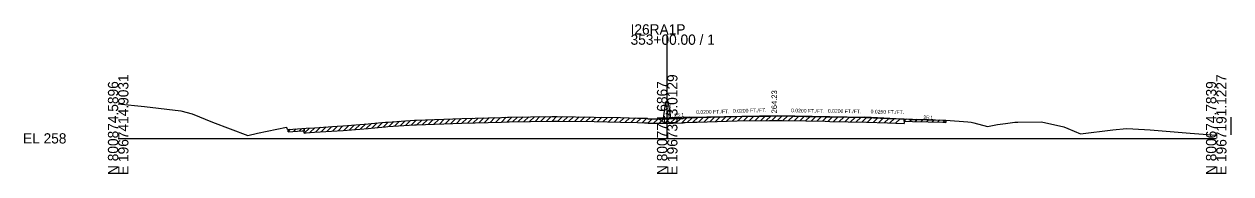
# Model space of a CAD drawing. Extents: x -26 to 304, y -10 to 7527.
# Drawn here: x -25.7 to 304, y 1490.3 to 1531.2 of the extents above; entities that cross this region are included whole.
import ezdxf

# ---------------------------------------------------------------- set-up
doc = ezdxf.new("R2010")
doc.units = 0
for name, color, linetype in [('RD_GPK_XS_Cell', 7, 'Continuous'), ('RD_XS_Base', 7, 'Continuous'), ('RD_XS_EarthShd', 7, 'Continuous'), ('RD_XS_ExGround', 7, 'Continuous'), ('RD_XS_ExPaveRet', 7, 'Continuous'), ('RD_XS_Misc_Line', 7, 'Continuous'), ('RD_XS_Pave', 7, 'Continuous'), ('RD_XS_PaveShd', 7, 'Continuous'), ('RD_XS_TX_Elev_EX', 7, 'Continuous'), ('RD_XS_TX_Elev_PR', 7, 'Continuous'), ('RD_XS_TX_MkPT', 7, 'Continuous'), ('RD_XS_TX_Profile', 7, 'Continuous'), ('RD_XS_TX_Station', 7, 'Continuous')]:
    doc.layers.add(name, color=color, linetype=linetype)

msp = doc.modelspace()

# ---------------------------------------------------------------- linework, layer by layer
at = {"layer": 'RD_GPK_XS_Cell'}
for p, q in [((150, 1500), (150, 1528.36)), ((0, 1500), (150, 1500)), ((150, 1500), (300, 1500))]:
    msp.add_line(p, q, dxfattribs=at)
at = {"layer": 'RD_XS_Base'}
msp.add_line((150, 1505.38), (150, 1505.51), dxfattribs=at)
at = {"layer": 'RD_XS_EarthShd'}
for p, q in [((149, 1505.53), (149.67, 1510.01)), ((150, 1510.01), (149.67, 1510.01)), ((150, 1510.01), (150.33, 1510.01)), ((151, 1505.53), (150.33, 1510.01))]:
    msp.add_line(p, q, dxfattribs=at)
at = {"layer": 'RD_XS_ExGround'}
msp.add_lwpolyline([(0, 1509.45), (7.22, 1508.68), (17.14, 1507.55), (20.26, 1506.67), (25.76, 1504.4), (35.44, 1500.79), (38.03, 1501.39), (46.02, 1503.04), (46.12, 1502.59), (46.44, 1502.45), (50.29, 1502.65), (51.38, 1502.76), (53.68, 1502.91), (59.81, 1503.34), (61.46, 1503.4), (68.3, 1503.99), (69.16, 1504.06), (73.08, 1504.4), (73.66, 1504.46), (80.92, 1504.93), (81.5, 1504.95), (93.87, 1505.39), (104.74, 1505.71), (106.37, 1505.77), (106.85, 1505.78), (118.51, 1505.99), (119.97, 1505.96), (130.09, 1505.82), (137.25, 1505.66), (141.88, 1505.56), (143.82, 1505.5), (144.5, 1505.48), (144.82, 1505.37), (145.25, 1505.36), (148.39, 1505.36), (150, 1505.38), (151.09, 1505.4), (151.59, 1505.41), (154.34, 1505.45), (154.55, 1505.57), (154.93, 1505.58), (157.3, 1505.67), (158.21, 1505.7), (169.08, 1506.01), (177.94, 1506.1), (181.29, 1506.13), (187.84, 1506.01), (193.12, 1505.92), (194.46, 1505.89), (204.49, 1505.67), (210.21, 1505.47), (217.02, 1505.24), (221.32, 1505.13), (225.33, 1505.01), (226.17, 1504.98), (232.13, 1504.48), (233.06, 1504.4), (233.8, 1504.22), (237.48, 1503.27), (240.28, 1503.75), (242.39, 1504.07), (244.94, 1504.45), (245.79, 1504.38), (252.3, 1504.48), (258.38, 1503.19), (259.46, 1502.71), (262.93, 1501.22), (271.75, 1502.35), (275.46, 1502.72), (277.21, 1502.62), (281.98, 1502.37), (292.92, 1501.4), (299.95, 1500.84), (300, 1500.83)], dxfattribs=at)
at = {"layer": 'RD_XS_ExPaveRet'}
for p, q in [((73.66, 1503.21), (80.92, 1503.68)), ((80.92, 1503.68), (81.5, 1503.7)), ((81.5, 1503.7), (93.87, 1504.14)), ((93.87, 1504.14), (104.74, 1504.46)), ((104.74, 1504.46), (106.37, 1504.52)), ((106.37, 1504.52), (106.85, 1504.53)), ((106.85, 1504.53), (118.51, 1504.74)), ((118.51, 1504.74), (119.97, 1504.71)), ((119.97, 1504.71), (130.09, 1504.57)), ((130.09, 1504.57), (137.25, 1504.41)), ((137.25, 1504.41), (141.88, 1504.31)), ((141.88, 1504.31), (143.82, 1504.25)), ((143.82, 1504.25), (144.5, 1504.23)), ((144.5, 1504.23), (144.82, 1504.12)), ((144.82, 1504.12), (145.25, 1504.11)), ((145.25, 1504.11), (148.39, 1504.11)), ((148.39, 1504.11), (150, 1504.13)), ((150, 1504.13), (151.09, 1504.15)), ((151.09, 1504.15), (151.59, 1504.16)), ((151.59, 1504.16), (154.34, 1504.2)), ((154.34, 1504.2), (154.55, 1504.32)), ((154.55, 1504.32), (154.93, 1504.33)), ((154.93, 1504.33), (157.3, 1504.42)), ((157.3, 1504.42), (158.21, 1504.45)), ((158.21, 1504.45), (169.08, 1504.76)), ((169.08, 1504.76), (177.94, 1504.85)), ((177.94, 1504.85), (181.29, 1504.88)), ((181.29, 1504.88), (187.84, 1504.76)), ((187.84, 1504.76), (193.12, 1504.67)), ((193.12, 1504.67), (194.46, 1504.64)), ((194.46, 1504.64), (204.49, 1504.42)), ((204.49, 1504.42), (210.21, 1504.22)), ((210.21, 1504.22), (214.76, 1504.06)), ((214.76, 1505.31), (214.76, 1504.06)), ((214.76, 1504.69), (214.76, 1505.31)), ((214.76, 1504.69), (217.02, 1504.61)), ((217.02, 1504.61), (221.32, 1504.5)), ((221.32, 1504.5), (225.33, 1504.38)), ((225.33, 1504.38), (226.17, 1504.35)), ((226.17, 1504.98), (226.17, 1504.35)), ((46.44, 1501.83), (46.44, 1502.45)), ((46.44, 1501.83), (50.29, 1502.03)), ((50.29, 1502.03), (50.85, 1502.08)), ((50.85, 1501.46), (50.85, 1502.71)), ((50.85, 1502.71), (50.85, 1502.08)), ((50.85, 1501.46), (51.38, 1501.51)), ((51.38, 1501.51), (53.68, 1501.66)), ((53.68, 1501.66), (59.81, 1502.09)), ((59.81, 1502.09), (61.46, 1502.15)), ((61.46, 1502.15), (68.3, 1502.74)), ((68.3, 1502.74), (69.16, 1502.81)), ((69.16, 1502.81), (73.08, 1503.15)), ((73.08, 1503.15), (73.66, 1503.21))]:
    msp.add_line(p, q, dxfattribs=at)
at = {"layer": 'RD_XS_Misc_Line'}
for p, q in [((60.08, 1502.1), (61.42, 1503.4)), ((61.62, 1502.17), (63.02, 1503.54)), ((63.16, 1502.3), (64.56, 1503.67)), ((64.69, 1502.43), (66.1, 1503.8)), ((66.23, 1502.57), (67.64, 1503.94)), ((67.77, 1502.7), (69.17, 1504.06)), ((69.31, 1502.82), (70.72, 1504.2)), ((70.85, 1502.96), (72.26, 1504.33)), ((72.39, 1503.09), (73.8, 1504.47)), ((73.93, 1503.23), (75.3, 1504.57)), ((75.46, 1503.33), (76.84, 1504.67)), ((77, 1503.43), (78.37, 1504.76)), ((78.54, 1503.52), (79.91, 1504.86)), ((80.08, 1503.62), (81.44, 1504.94)), ((81.62, 1503.7), (82.95, 1505)), ((83.16, 1503.76), (84.49, 1505.05)), ((84.7, 1503.81), (86.03, 1505.11)), ((86.23, 1503.87), (87.57, 1505.17)), ((87.77, 1503.92), (89.1, 1505.22)), ((89.31, 1503.98), (90.64, 1505.28)), ((90.85, 1504.03), (92.18, 1505.33)), ((92.39, 1504.09), (93.72, 1505.39)), ((93.93, 1504.15), (95.25, 1505.43)), ((95.47, 1504.19), (96.79, 1505.48)), ((97, 1504.24), (98.33, 1505.53)), ((98.54, 1504.28), (99.86, 1505.57)), ((100.08, 1504.33), (101.4, 1505.62)), ((101.62, 1504.37), (102.94, 1505.66)), ((103.16, 1504.42), (104.48, 1505.71)), ((104.7, 1504.46), (106.02, 1505.75)), ((106.24, 1504.51), (107.55, 1505.79)), ((107.77, 1504.54), (109.08, 1505.82)), ((109.31, 1504.57), (110.62, 1505.84)), ((110.85, 1504.6), (112.16, 1505.87)), ((112.39, 1504.63), (113.7, 1505.9)), ((113.93, 1504.65), (115.23, 1505.93)), ((115.47, 1504.68), (116.77, 1505.95)), ((117.01, 1504.71), (118.31, 1505.98)), ((118.54, 1504.74), (119.8, 1505.96)), ((120.08, 1504.71), (121.35, 1505.94)), ((121.62, 1504.69), (122.88, 1505.92)), ((123.16, 1504.67), (124.42, 1505.9)), ((124.7, 1504.64), (125.96, 1505.88)), ((126.24, 1504.62), (127.5, 1505.85)), ((127.78, 1504.6), (129.04, 1505.83)), ((129.31, 1504.58), (130.57, 1505.81)), ((130.85, 1504.55), (132.11, 1505.77)), ((132.39, 1504.52), (133.65, 1505.74)), ((133.93, 1504.48), (135.18, 1505.7)), ((135.47, 1504.45), (136.72, 1505.67)), ((137.01, 1504.42), (138.26, 1505.64)), ((138.55, 1504.38), (139.8, 1505.6)), ((140.08, 1504.35), (141.34, 1505.57)), ((141.62, 1504.31), (142.87, 1505.53)), ((143.16, 1504.27), (144.4, 1505.48)), ((144.7, 1504.16), (145.93, 1505.36)), ((146.24, 1504.11), (147.52, 1505.36)), ((147.78, 1504.11), (149.07, 1505.37)), ((149.32, 1504.12), (150.62, 1505.39)), ((150.85, 1504.15), (152.15, 1505.41)), ((152.39, 1504.17), (153.69, 1505.44)), ((153.93, 1504.19), (155.38, 1505.6)), ((155.47, 1504.35), (156.8, 1505.65)), ((157.01, 1504.41), (158.33, 1505.7)), ((158.55, 1504.46), (159.87, 1505.74)), ((160.09, 1504.5), (161.41, 1505.79)), ((161.62, 1504.54), (162.94, 1505.83)), ((163.16, 1504.59), (164.48, 1505.88)), ((164.7, 1504.63), (166.02, 1505.92)), ((166.24, 1504.68), (167.56, 1505.96)), ((167.78, 1504.72), (169.1, 1506.01)), ((169.32, 1504.76), (170.61, 1506.02)), ((170.86, 1504.78), (172.15, 1506.04)), ((172.39, 1504.79), (173.69, 1506.05)), ((173.93, 1504.81), (175.23, 1506.07)), ((175.47, 1504.82), (176.77, 1506.08)), ((177.01, 1504.84), (178.3, 1506.1)), ((178.55, 1504.85), (179.84, 1506.11)), ((180.09, 1504.87), (181.38, 1506.12)), ((181.63, 1504.87), (182.89, 1506.1)), ((183.16, 1504.84), (184.42, 1506.07)), ((184.7, 1504.82), (185.96, 1506.05)), ((186.24, 1504.79), (187.5, 1506.02)), ((187.78, 1504.76), (189.04, 1505.99)), ((189.32, 1504.74), (190.58, 1505.96)), ((190.86, 1504.71), (192.12, 1505.94)), ((192.4, 1504.68), (193.65, 1505.91)), ((193.93, 1504.65), (195.19, 1505.87)), ((195.47, 1504.61), (196.73, 1505.84)), ((197.01, 1504.58), (198.27, 1505.8)), ((198.55, 1504.55), (199.8, 1505.77)), ((200.09, 1504.51), (201.34, 1505.73)), ((201.63, 1504.48), (202.88, 1505.7)), ((203.17, 1504.44), (204.42, 1505.67)), ((204.7, 1504.41), (205.94, 1505.62)), ((206.24, 1504.35), (207.48, 1505.56)), ((207.78, 1504.3), (209.02, 1505.51)), ((209.32, 1504.25), (210.56, 1505.46)), ((210.86, 1504.2), (212.1, 1505.4)), ((212.4, 1504.14), (213.64, 1505.35)), ((214.76, 1504.69), (215.38, 1505.29)), ((216.28, 1504.64), (216.9, 1505.24)), ((217.8, 1504.59), (218.42, 1505.2)), ((219.33, 1504.55), (219.94, 1505.16)), ((220.85, 1504.52), (221.46, 1505.12)), ((222.37, 1504.47), (222.98, 1505.08)), ((223.89, 1504.42), (224.5, 1505.03)), ((225.41, 1504.38), (226.02, 1504.98)), ((46.44, 1501.83), (47.11, 1502.49)), ((47.96, 1501.91), (48.63, 1502.57)), ((49.48, 1501.99), (50.15, 1502.65)), ((50.85, 1501.46), (52.24, 1502.81)), ((52.39, 1501.57), (53.76, 1502.91)), ((53.92, 1501.67), (55.31, 1503.02)), ((55.46, 1501.78), (56.84, 1503.13)), ((57, 1501.89), (58.38, 1503.24)), ((58.54, 1502), (59.92, 1503.34))]:
    msp.add_line(p, q, dxfattribs=at)
at = {"layer": 'RD_XS_Pave'}
for p, q in [((156, 1505.75), (180, 1506.23)), ((180, 1506.23), (204, 1505.75)), ((216, 1505.17), (204, 1505.75)), ((304, 1505.75), (304, 1500.96))]:
    msp.add_line(p, q, dxfattribs=at)
at = {"layer": 'RD_XS_PaveShd'}
for p, q in [((156, 1505.75), (150, 1505.51)), ((216, 1505.17), (226, 1504.98))]:
    msp.add_line(p, q, dxfattribs=at)
at = {"layer": 'RD_XS_TX_Elev_PR'}
for p, q in [((150, 1505.38), (151.09, 1505.4)), ((151.09, 1505.4), (151.59, 1505.41)), ((151.59, 1505.41), (154.34, 1505.45)), ((154.34, 1505.45), (154.55, 1505.57)), ((154.55, 1505.57), (154.93, 1505.58)), ((154.93, 1505.58), (157.3, 1505.67)), ((157.3, 1505.67), (158.21, 1505.7)), ((158.21, 1505.7), (169.08, 1506.01)), ((169.08, 1506.01), (177.94, 1506.1)), ((177.94, 1506.1), (181.29, 1506.13)), ((181.29, 1506.13), (187.84, 1506.01)), ((187.84, 1506.01), (193.12, 1505.92)), ((193.12, 1505.92), (194.46, 1505.89)), ((194.46, 1505.89), (204.49, 1505.67)), ((204.49, 1505.67), (210.21, 1505.47)), ((210.21, 1505.47), (214.76, 1505.31)), ((214.76, 1505.31), (217.02, 1505.24)), ((217.02, 1505.24), (219.17, 1505.18)), ((219.17, 1505.18), (221.32, 1505.13)), ((221.32, 1505.13), (223.32, 1505.07)), ((223.32, 1505.07), (225.33, 1505.01)), ((225.33, 1505.01), (226, 1504.98))]:
    msp.add_line(p, q, dxfattribs=at)

# ---------------------------------------------------------------- texts
at = {"layer": 'RD_GPK_XS_Cell'}
for s, p in [('I26RA1P', (140, 1528.36)), ('353+00.00 / 1', (140, 1525.56)), ('EL 258', (-26, 1498.6))]:
    msp.add_text(s, height=2.8, dxfattribs=at).set_placement(p)
for s, p in [('E 1967414.9031', (2.8, 1490)), ('E 1967303.0129', (152.8, 1490)), ('E 1967191.1227', (302.8, 1490)), ('N 800874.5896', (0, 1490)), ('N 800774.6867', (150, 1490)), ('N 800674.7839', (300, 1490))]:
    msp.add_text(s, height=2.8, rotation=90, dxfattribs=at).set_placement(p)
at = {"layer": 'RD_XS_TX_Elev_EX'}
msp.add_text('263.38', height=1, rotation=90, dxfattribs=at).set_placement((151, 1505.38))
at = {"layer": 'RD_XS_TX_MkPT'}
for rotation, p in [(2.2906, (151.94, 1505.83)), (357.7094, (219.96, 1505.26))]:
    msp.add_text('25:1', height=1, rotation=rotation, dxfattribs=at).set_placement(p)
at = {"layer": 'RD_XS_TX_Profile'}
for s, rotation, p in [('0.0200 FT./FT.', 1.1458, (157.92, 1506.67)), ('0.0200 FT./FT.', 1.1458, (167.98, 1506.99)), ('0.0200 FT./FT.', 358.5679, (183.83, 1507.13)), ('0.0200 FT./FT.', 358.8542, (193.89, 1507.03)), ('0.0250 FT./FT.', 358.8542, (205.57, 1506.83))]:
    msp.add_text(s, height=1, rotation=rotation, dxfattribs=at).set_placement(p)
at = {"layer": 'RD_XS_TX_Station'}
msp.add_text(' 264.23', height=1.5, rotation=90, dxfattribs=at).set_placement((180, 1506.23))

doc.saveas('drawing.dxf')
